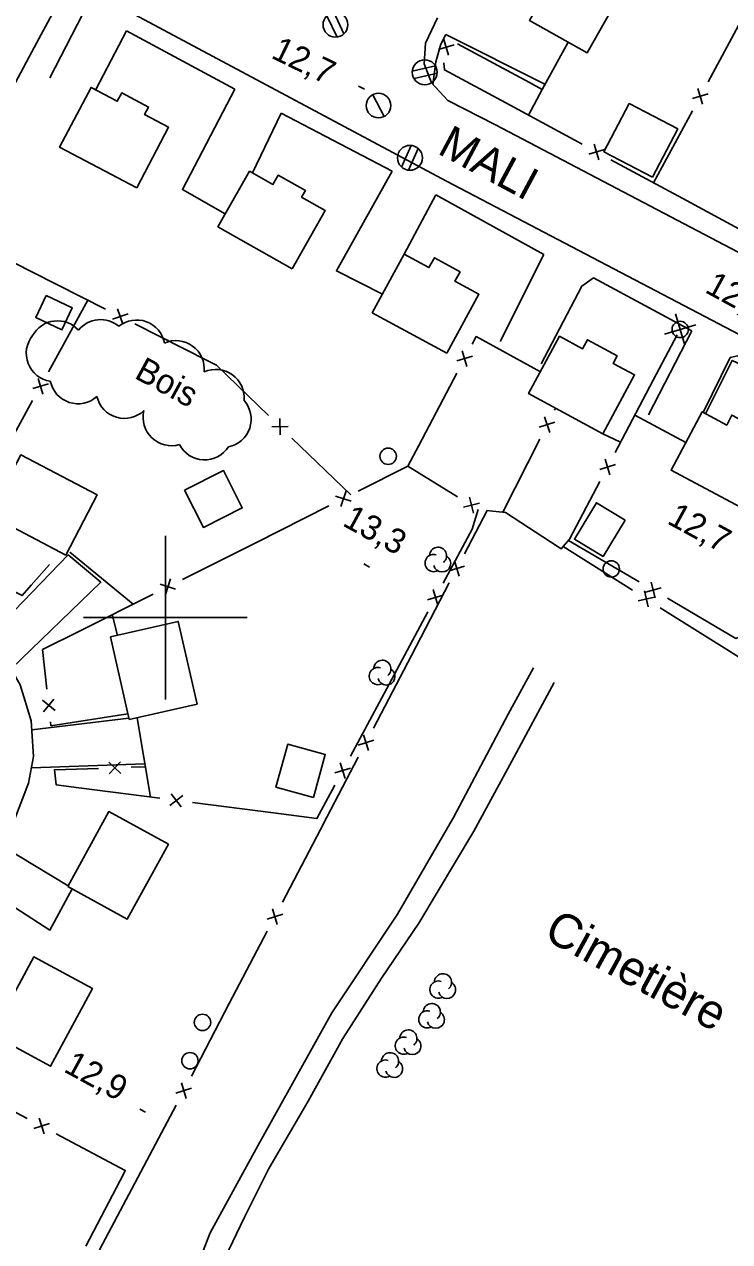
# Model space of a CAD drawing. Extents: x 219136 to 222520, y 5421589 to 5424530.
# Drawn here: x 220582.8 to 220669, y 5423523.8 to 5423672.5 of the extents above; entities that cross this region are included whole.
import ezdxf

# ---------------------------------------------------------------- set-up
doc = ezdxf.new("R2010")
doc.units = 0
for name, color, linetype in [('Level 19', 7, 'Continuous'), ('Level 21', 7, 'Continuous'), ('Level 3', 7, 'Continuous'), ('Level 31', 7, 'Continuous'), ('Level 36', 7, 'Continuous'), ('Level 37', 7, 'Continuous'), ('Level 44', 7, 'Continuous'), ('Level 52', 7, 'Continuous'), ('Level 61', 7, 'Continuous')]:
    doc.layers.add(name, color=color, linetype=linetype)

msp = doc.modelspace()

# ---------------------------------------------------------------- linework, layer by layer
at = {"layer": 'Level 19'}
for points in [[(220590.57, 5423675.02), (220585.89, 5423665.96)], [(220595.24, 5423671.69), (220591.51, 5423664.54)], [(220646.39, 5423665.16), (220634.28, 5423671.24)], [(220608.5, 5423664.56), (220602.09, 5423652.3), (220607.32, 5423649.33)], [(220610.64, 5423654.34), (220614.16, 5423661.62)], [(220627.72, 5423654.56), (220620.91, 5423642.35), (220626.52, 5423639.51)], [(220629.19, 5423644.41), (220633.04, 5423651.67)], [(220646.27, 5423644.36), (220640.91, 5423633.75)], [(220645.92, 5423631.01), (220650.91, 5423640.51), (220652.31, 5423641.53)], [(220664.36, 5423635.02), (220659.04, 5423624.78)], [(220665.72, 5423625.05), (220669.04, 5423631.76), (220669.96, 5423631.99)], [(220581.16, 5423593.72), (220592.12, 5423604.31), (220588.13, 5423607.66), (220578.21, 5423597.46)], [(220677.26, 5423439.13), (220673.4, 5423441.75), (220667.19, 5423445.95), (220659.5, 5423450.1), (220648.79, 5423456.42), (220637.57, 5423462.4), (220628.98, 5423466.65), (220621.26, 5423469.59), (220614.32, 5423472.49), (220608.83, 5423475.28), (220604.62, 5423479.01), (220601.77, 5423483.41), (220599.74, 5423489.66), (220599.04, 5423497.72), (220600.51, 5423508.16), (220602.83, 5423518.02), (220605.47, 5423524.83), (220611.33, 5423535.54), (220620.35, 5423551.71), (220628.37, 5423563.76), (220635.22, 5423575.59), (220641.88, 5423588.2), (220645.01, 5423593.87)], [(220647.52, 5423592.07), (220642.33, 5423582.44), (220637.71, 5423573.89), (220630.99, 5423562.66), (220626.4, 5423555.95), (220621.71, 5423548.58), (220617.47, 5423540.91), (220612.62, 5423532.59), (220609.69, 5423526.75), (220607.25, 5423521.72)], [(220595.54, 5423587.72), (220583.69, 5423586.27)], [(220583.63, 5423581.64), (220597.5, 5423582.15)], [(220588.11, 5423567.23), (220579.88, 5423572.2)], [(220577.27, 5423567.33), (220585.89, 5423561.82), (220588.61, 5423566.86)]]:
    msp.add_lwpolyline(points, dxfattribs=at)
at = {"layer": 'Level 21'}
for points in [[(220802, 5423680.11), (220800.96, 5423683.18), (220800.01, 5423684.27), (220798.11, 5423685.47), (220757.72, 5423706.74), (220744.58, 5423713.57), (220742.85, 5423713.77), (220741.02, 5423713.4), (220739.43, 5423712.6), (220738.05, 5423711.53), (220737.2, 5423709.97), (220720.08, 5423677.36), (220698.75, 5423637.17), (220695.73, 5423633.62), (220692.16, 5423631.21), (220687.35, 5423629.45), (220684.13, 5423629.04), (220682, 5423629.28), (220679.93, 5423629.8), (220678.67, 5423630.1), (220634.34, 5423653.3), (220590.27, 5423676.88)], [(220554.46, 5423688.81), (220539.92, 5423660.77), (220524.68, 5423632.17), (220524.21, 5423630.58), (220524.06, 5423629.15), (220524.56, 5423627.28), (220525.37, 5423626.07), (220526.84, 5423624.87), (220560.06, 5423607.83), (220573.19, 5423600.82), (220577.54, 5423598.1), (220580.07, 5423595.65), (220582.25, 5423591.8), (220583.62, 5423587.37), (220583.89, 5423583.02), (220583.28, 5423579.78), (220581.6, 5423575.4), (220554.2, 5423524.37), (220519.39, 5423458.76)], [(220633.28, 5423673.26), (220631.81, 5423670.17), (220631.65, 5423667.65), (220632.53, 5423665.32), (220634.52, 5423663.18), (220640.34, 5423660.19), (220680.65, 5423639.06)], [(220608.5, 5423664.56), (220595.24, 5423671.69)], [(220632.7, 5423665.14), (220633.05, 5423667.91), (220633.68, 5423670.05), (220634.28, 5423671.24)], [(220627.72, 5423654.56), (220614.16, 5423661.62)], [(220646.27, 5423644.36), (220633.04, 5423651.67)], [(220664.36, 5423635.02), (220652.31, 5423641.53)]]:
    msp.add_lwpolyline(points, dxfattribs=at)
at = {"layer": 'Level 3'}
for p, q in [((220623.62, 5423664.93), (220624.32, 5423664.55)), ((220624.26, 5423606.56), (220624.96, 5423606.18)), ((220596.88, 5423539.95), (220597.58, 5423539.57))]:
    msp.add_line(p, q, dxfattribs=at)
at = {"layer": 'Level 31'}
for points in [[(220656.55, 5423677.89), (220651.54, 5423668.99), (220644.5, 5423672.96), (220646.08, 5423675.77), (220644.33, 5423676.76), (220646.14, 5423679.96), (220647.87, 5423678.99), (220649.49, 5423681.87)], [(220596.5, 5423652.51), (220587.07, 5423657.49), (220590.92, 5423664.78), (220594.12, 5423663.08), (220594.67, 5423664.11), (220597.96, 5423662.37), (220597.47, 5423661.45), (220600.4, 5423659.9)], [(220659.54, 5423653.81), (220653.6, 5423656.91), (220656.69, 5423662.8), (220662.62, 5423659.7)], [(220615.48, 5423642.62), (220606.43, 5423647.76), (220610.29, 5423654.54), (220613.15, 5423652.92), (220613.8, 5423654.05), (220617.11, 5423652.17), (220616.65, 5423651.37), (220619.52, 5423649.74)], [(220634.39, 5423632.29), (220625.29, 5423637.25), (220629.19, 5423644.41), (220632.22, 5423642.76), (220632.88, 5423643.96), (220636.02, 5423642.24), (220635.39, 5423641.1), (220638.32, 5423639.5)], [(220585.42, 5423639.34), (220588.62, 5423637.84), (220587.36, 5423635.15), (220584.16, 5423636.65)], [(220653.45, 5423622.46), (220644.39, 5423627.36), (220648.18, 5423634.37), (220650.99, 5423632.85), (220651.59, 5423633.95), (220655.21, 5423631.99), (220654.71, 5423631.06), (220657.34, 5423629.64)], [(220670.91, 5423613.16), (220661.81, 5423618.02), (220665.59, 5423625.12), (220668.6, 5423623.51), (220669.25, 5423624.74), (220672.7, 5423622.9), (220672.11, 5423621.79), (220674.76, 5423620.38)], [(220587.85, 5423607.64), (220578.48, 5423612.54), (220582.32, 5423619.88), (220591.68, 5423614.98)], [(220602.36, 5423615.57), (220607.09, 5423617.95), (220609.39, 5423613.4), (220604.66, 5423611.01)], [(220656.19, 5423611.91), (220653.49, 5423607.47), (220649.99, 5423609.6), (220652.69, 5423614.04)], [(220595.58, 5423587.54), (220593.28, 5423597.63), (220601.56, 5423599.53), (220603.87, 5423589.43)], [(220618.1, 5423578.03), (220613.52, 5423579.29), (220614.96, 5423584.53), (220619.54, 5423583.27)], [(220588.07, 5423567.16), (220593.09, 5423576.3), (220600.37, 5423572.3), (220595.35, 5423563.16)], [(220578.79, 5423549.05), (220583.91, 5423558.55), (220591.09, 5423554.68), (220585.97, 5423545.18)]]:
    msp.add_lwpolyline(points, close=True, dxfattribs=at)
at = {"layer": 'Level 36'}
for p, q in [((220619.75, 5423673.54), (220621, 5423670.92)), ((220621.83, 5423671.34), (220620.58, 5423673.96)), ((220633.01, 5423667.41), (220630.18, 5423666.75)), ((220630.41, 5423665.85), (220633.24, 5423666.51)), ((220626.76, 5423661.22), (220625.36, 5423663.88)), ((220630.05, 5423657.67), (220628.86, 5423655.02)), ((220629.71, 5423654.67), (220630.9, 5423657.32)), ((220661, 5423634.63), (220664.83, 5423635.76)), ((220663.48, 5423633.28), (220662.35, 5423637.11))]:
    msp.add_line(p, q, dxfattribs=at)
for centre, radius in [((220620.79, 5423672.43), 1.52), ((220631.7, 5423666.63), 1.52), ((220626.05, 5423662.56), 1.5), ((220629.89, 5423656.17), 1.52), ((220662.92, 5423635.2), 1), ((220627.23, 5423619.71), 1), ((220654.5, 5423605.95), 1), ((220604.54, 5423550.54), 1), ((220603.01, 5423545.86), 1)]:
    msp.add_circle(centre, radius, dxfattribs=at)
at = {"layer": 'Level 37'}
for p, q in [((220635.3, 5423669.96), (220633.37, 5423669.4)), ((220634.61, 5423668.71), (220634.05, 5423670.64)), ((220665.66, 5423662.73), (220665.09, 5423664.64)), ((220666.34, 5423663.97), (220664.42, 5423663.4)), ((220653.66, 5423657.18), (220651.74, 5423656.61)), ((220652.41, 5423657.85), (220652.99, 5423655.93)), ((220594.17, 5423637.74), (220594.8, 5423635.84)), ((220595.44, 5423637.1), (220593.53, 5423636.48)), ((220635.61, 5423631.35), (220637.52, 5423631.94)), ((220636.27, 5423632.6), (220636.86, 5423630.69)), ((220583.79, 5423627.99), (220585.71, 5423628.55)), ((220584.47, 5423629.23), (220585.03, 5423627.31)), ((220614.01, 5423624.32), (220614.04, 5423622.32)), ((220647.6, 5423623.89), (220645.7, 5423623.26)), ((220646.97, 5423622.62), (220646.34, 5423624.53)), ((220615.03, 5423623.34), (220613.02, 5423623.31)), ((220655, 5423618.69), (220653.08, 5423618.1)), ((220654.34, 5423617.44), (220653.74, 5423619.35)), ((220621.45, 5423613.59), (220622.08, 5423615.49)), ((220622.71, 5423614.22), (220620.81, 5423614.85)), ((220636.43, 5423613.5), (220638.38, 5423613.97)), ((220637.64, 5423612.76), (220637.17, 5423614.7)), ((220636.58, 5423606.3), (220634.67, 5423605.7)), ((220635.92, 5423605.04), (220635.32, 5423606.95)), ((220600, 5423602.82), (220600.63, 5423604.72)), ((220601.26, 5423603.46), (220599.36, 5423604.09)), ((220632.72, 5423603.42), (220633.3, 5423601.5)), ((220659, 5423601.3), (220658.56, 5423603.26)), ((220658.66, 5423603.12), (220660.6, 5423603.62)), ((220659.88, 5423602.4), (220659.37, 5423604.34)), ((220632.05, 5423602.17), (220633.96, 5423602.75)), ((220657.8, 5423602.06), (220659.76, 5423602.5)), ((220586.53, 5423588.63), (220584.97, 5423589.89)), ((220586.38, 5423590.04), (220585.12, 5423588.48)), ((220624.81, 5423583.77), (220624.21, 5423585.69)), ((220625.46, 5423585.03), (220623.55, 5423584.43)), ((220594.57, 5423580.96), (220593.11, 5423582.33)), ((220593.15, 5423580.91), (220594.52, 5423582.38)), ((220621.38, 5423582.26), (220621.96, 5423580.35)), ((220620.71, 5423581.02), (220622.63, 5423581.59)), ((220602.12, 5423578.28), (220600.53, 5423577.05)), ((220600.72, 5423578.46), (220601.94, 5423576.87)), ((220613.68, 5423562.51), (220613.08, 5423564.42)), ((220614.34, 5423563.76), (220612.43, 5423563.16)), ((220603.21, 5423542.5), (220601.3, 5423541.9)), ((220602.55, 5423541.24), (220601.96, 5423543.15)), ((220583.93, 5423537.58), (220585.84, 5423538.17)), ((220585.18, 5423536.92), (220584.59, 5423538.83))]:
    msp.add_line(p, q, dxfattribs=at)
for points in [[(220583.68, 5423669.13), (220586.77, 5423674.88), (220583.69, 5423676.48)], [(220666.33, 5423665.44), (220670.92, 5423673.93)], [(220635.69, 5423670.09), (220644.5, 5423665.36)], [(220644.5, 5423665.36), (220646.04, 5423664.53), (220649.24, 5423670.29)], [(220578.94, 5423660.32), (220583.68, 5423669.13)], [(220642.14, 5423662.59), (220634.11, 5423666.92), (220634.02, 5423667.79)], [(220646.04, 5423664.53), (220644.39, 5423661.37)], [(220650.94, 5423657.84), (220642.14, 5423662.59)], [(220659.67, 5423653.13), (220664.43, 5423661.93)], [(220663.26, 5423651.19), (220654.46, 5423655.94)], [(220672.06, 5423646.45), (220663.26, 5423651.19)], [(220583.77, 5423642.2), (220574.85, 5423646.71)], [(220592.7, 5423637.69), (220583.77, 5423642.2)], [(220590.54, 5423638.78), (220585.71, 5423630.02)], [(220605.19, 5423631.38), (220596.27, 5423635.89)], [(220645.84, 5423630.04), (220637.99, 5423634.34), (220637.5, 5423633.41)], [(220659.63, 5423629.01), (220662.54, 5423634.53)], [(220612.59, 5423624.71), (220606.24, 5423630.85), (220605.19, 5423631.38)], [(220672.63, 5423629.86), (220669.28, 5423631.43), (220666.46, 5423625.8)], [(220635.63, 5423629.87), (220630.97, 5423621.03)], [(220654.97, 5423620.16), (220659.63, 5423629.01)], [(220583.78, 5423626.52), (220578.95, 5423617.76)], [(220647.55, 5423625.36), (220647.67, 5423625.59)], [(220666.46, 5423625.8), (220666.01, 5423624.89)], [(220657.38, 5423624.73), (220663.62, 5423621.41)], [(220655.63, 5423621.42), (220653.45, 5423622.46)], [(220622.65, 5423614.98), (220615.46, 5423621.93)], [(220630.97, 5423621.03), (220629.62, 5423618.48), (220635.69, 5423614.77)], [(220641.25, 5423612.86), (220645.75, 5423621.79)], [(220623.55, 5423615.43), (220629.62, 5423618.48)], [(220647.99, 5423608.63), (220648.37, 5423608.38), (220649.39, 5423609.57), (220653.11, 5423616.62)], [(220611.04, 5423609.15), (220619.97, 5423613.64)], [(220638.24, 5423613.22), (220637.48, 5423610.81), (220633.95, 5423604.22)], [(220636.55, 5423607.77), (220639.33, 5423613.09)], [(220639.25, 5423613.1), (220641.58, 5423612.82), (220647.99, 5423608.63)], [(220602.1, 5423604.67), (220611.04, 5423609.15)], [(220649.27, 5423609.43), (220649.28, 5423609.43), (220657.9, 5423604.38)], [(220596.05, 5423601.63), (220588.34, 5423607.99)], [(220648.63, 5423608.68), (220657.09, 5423603.35)], [(220575.06, 5423606.39), (220582.49, 5423602.68), (220583.61, 5423603.95)], [(220583.61, 5423603.95), (220585.84, 5423606.47)], [(220630.07, 5423595.36), (220634.7, 5423604.23)], [(220589.59, 5423598.39), (220598.52, 5423602.88)], [(220661.35, 5423602.36), (220669.72, 5423597.46), (220670.01, 5423597.55)], [(220593.5, 5423600.36), (220594.14, 5423597.83)], [(220632.06, 5423600.7), (220627.34, 5423591.88)], [(220660.47, 5423601.21), (220668.93, 5423595.88)], [(220585.53, 5423591.25), (220585, 5423596.09), (220589.59, 5423598.39)], [(220668.93, 5423595.88), (220674.28, 5423592.51), (220677.42, 5423590.59)], [(220625.43, 5423586.5), (220630.07, 5423595.36)], [(220627.34, 5423591.88), (220622.62, 5423583.07)], [(220595.42, 5423588.26), (220586.02, 5423586.79), (220585.97, 5423587.27)], [(220598.18, 5423578.07), (220596.57, 5423587.76)], [(220618.95, 5423574.1), (220619.75, 5423575.63), (220623.58, 5423582.96)], [(220589.43, 5423579.2), (220586.67, 5423579.56), (220586.47, 5423581.4), (220591.84, 5423581.58)], [(220595.84, 5423581.71), (220597.57, 5423581.77)], [(220620.73, 5423579.54), (220618.53, 5423575.44), (220613.23, 5423576.13)], [(220599.34, 5423577.92), (220589.43, 5423579.2)], [(220613.23, 5423576.13), (220603.31, 5423577.41)], [(220614.31, 5423565.24), (220618.95, 5423574.1)], [(220607.82, 5423552.83), (220612.46, 5423561.69)], [(220603.18, 5423543.97), (220607.82, 5423552.83)], [(220574.29, 5423543.5), (220583.12, 5423538.81)], [(220596.64, 5423531.6), (220601.33, 5423540.43)], [(220586.65, 5423536.94), (220595.11, 5423532.45), (220594.91, 5423532.07)], [(220594.91, 5423532.07), (220590.27, 5423523.22)], [(220591.94, 5423522.76), (220596.64, 5423531.6)]]:
    msp.add_lwpolyline(points, dxfattribs=at)
at = {"layer": 'Level 44'}
for centre, radius, start, end in [((220586.81, 5423632.8), 3.46, 42.2165, 151.3881), ((220592.07, 5423632.95), 3.46, 49.6376, 140.9507), ((220596.5, 5423632.9), 3.46, 10.8379, 129.1003), ((220586.47, 5423632.29), 3.46, 141.1936, 261.1936), ((220601.3, 5423630.38), 3.46, 353.9359, 113.9359), ((220606.18, 5423626.86), 3.46, 354.4218, 114.4218), ((220589.33, 5423629.58), 3.46, 191.8045, 311.8045), ((220595.01, 5423627.8), 3.46, 193.4106, 313.4106), ((220607.03, 5423624.24), 3.46, 281.4201, 41.4201), ((220600.75, 5423624.46), 3.46, 166.2385, 286.2385), ((220604.8, 5423622.72), 3.46, 207.2246, 327.2246), ((220632.78, 5423606.66), 1.05, 72.005, 297.6935), ((220633.33, 5423607.55), 1.05, 310.1588, 177.6158), ((220633.82, 5423606.62), 1.05, 194.8265, 57.5108), ((220626.52, 5423593.74), 1.05, 310.1588, 177.6158), ((220625.97, 5423592.85), 1.05, 72.005, 297.6935), ((220627.01, 5423592.81), 1.05, 194.8265, 57.5108), ((220633.38, 5423554.55), 1.05, 72.005, 297.6935), ((220633.93, 5423555.44), 1.05, 310.1588, 177.6158), ((220634.42, 5423554.51), 1.05, 194.8265, 57.5108), ((220632.56, 5423551.8), 1.05, 310.1588, 177.6158), ((220632.01, 5423550.91), 1.05, 72.005, 297.6935), ((220633.05, 5423550.87), 1.05, 194.8265, 57.5108), ((220629.7, 5423548.58), 1.05, 310.1588, 177.6158), ((220629.15, 5423547.69), 1.05, 72.005, 297.6935), ((220630.19, 5423547.65), 1.05, 194.8265, 57.5108), ((220627.46, 5423545.79), 1.05, 310.1588, 177.6158), ((220626.91, 5423544.9), 1.05, 72.005, 297.6935), ((220627.95, 5423544.86), 1.05, 194.8265, 57.5108)]:
    msp.add_arc(centre, radius, start, end, dxfattribs=at)
at = {"layer": 'Level 61'}
for points in [[(220600, 5423610), (220600, 5423600), (220600, 5423590)], [(220590, 5423600), (220600, 5423600), (220610, 5423600)]]:
    msp.add_lwpolyline(points, dxfattribs=at)

# ---------------------------------------------------------------- texts
at = {"layer": 'Level 21'}
msp.add_text('MALI', height=4, rotation=331.8506, dxfattribs=at).set_placement((220633.11, 5423656.77))
at = {"layer": 'Level 3'}
for s, rotation, p in [('12,7', 333.9516, (220612.8, 5423668.44)), ('12,5', 331.383, (220665.81, 5423639.81)), ('13,3', 331.383, (220621.52, 5423611.3)), ('12,7', 331.383, (220661.19, 5423611.56)), ('12,9', 331.383, (220587.44, 5423544.59))]:
    msp.add_text(s, height=3, rotation=rotation, dxfattribs=at).set_placement(p)
at = {"layer": 'Level 44'}
msp.add_text('Bois', height=3, rotation=331.3547, dxfattribs=at).set_placement((220596.08, 5423629.33))
at = {"layer": 'Level 52'}
msp.add_text('Cimetière', height=4.2, rotation=331.383, dxfattribs=at).set_placement((220646.07, 5423560.84))

doc.saveas('drawing.dxf')
